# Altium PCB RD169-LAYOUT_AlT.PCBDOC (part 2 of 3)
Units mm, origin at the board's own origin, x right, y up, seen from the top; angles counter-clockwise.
Board outline 192 x 135 mm, 2 copper layers (TOP, BOTTOM), stack 0 mm thick; 266 components, 140 nets, 1304 pads, 0 vias.
Unrouted connection lines stored in the file: 1.
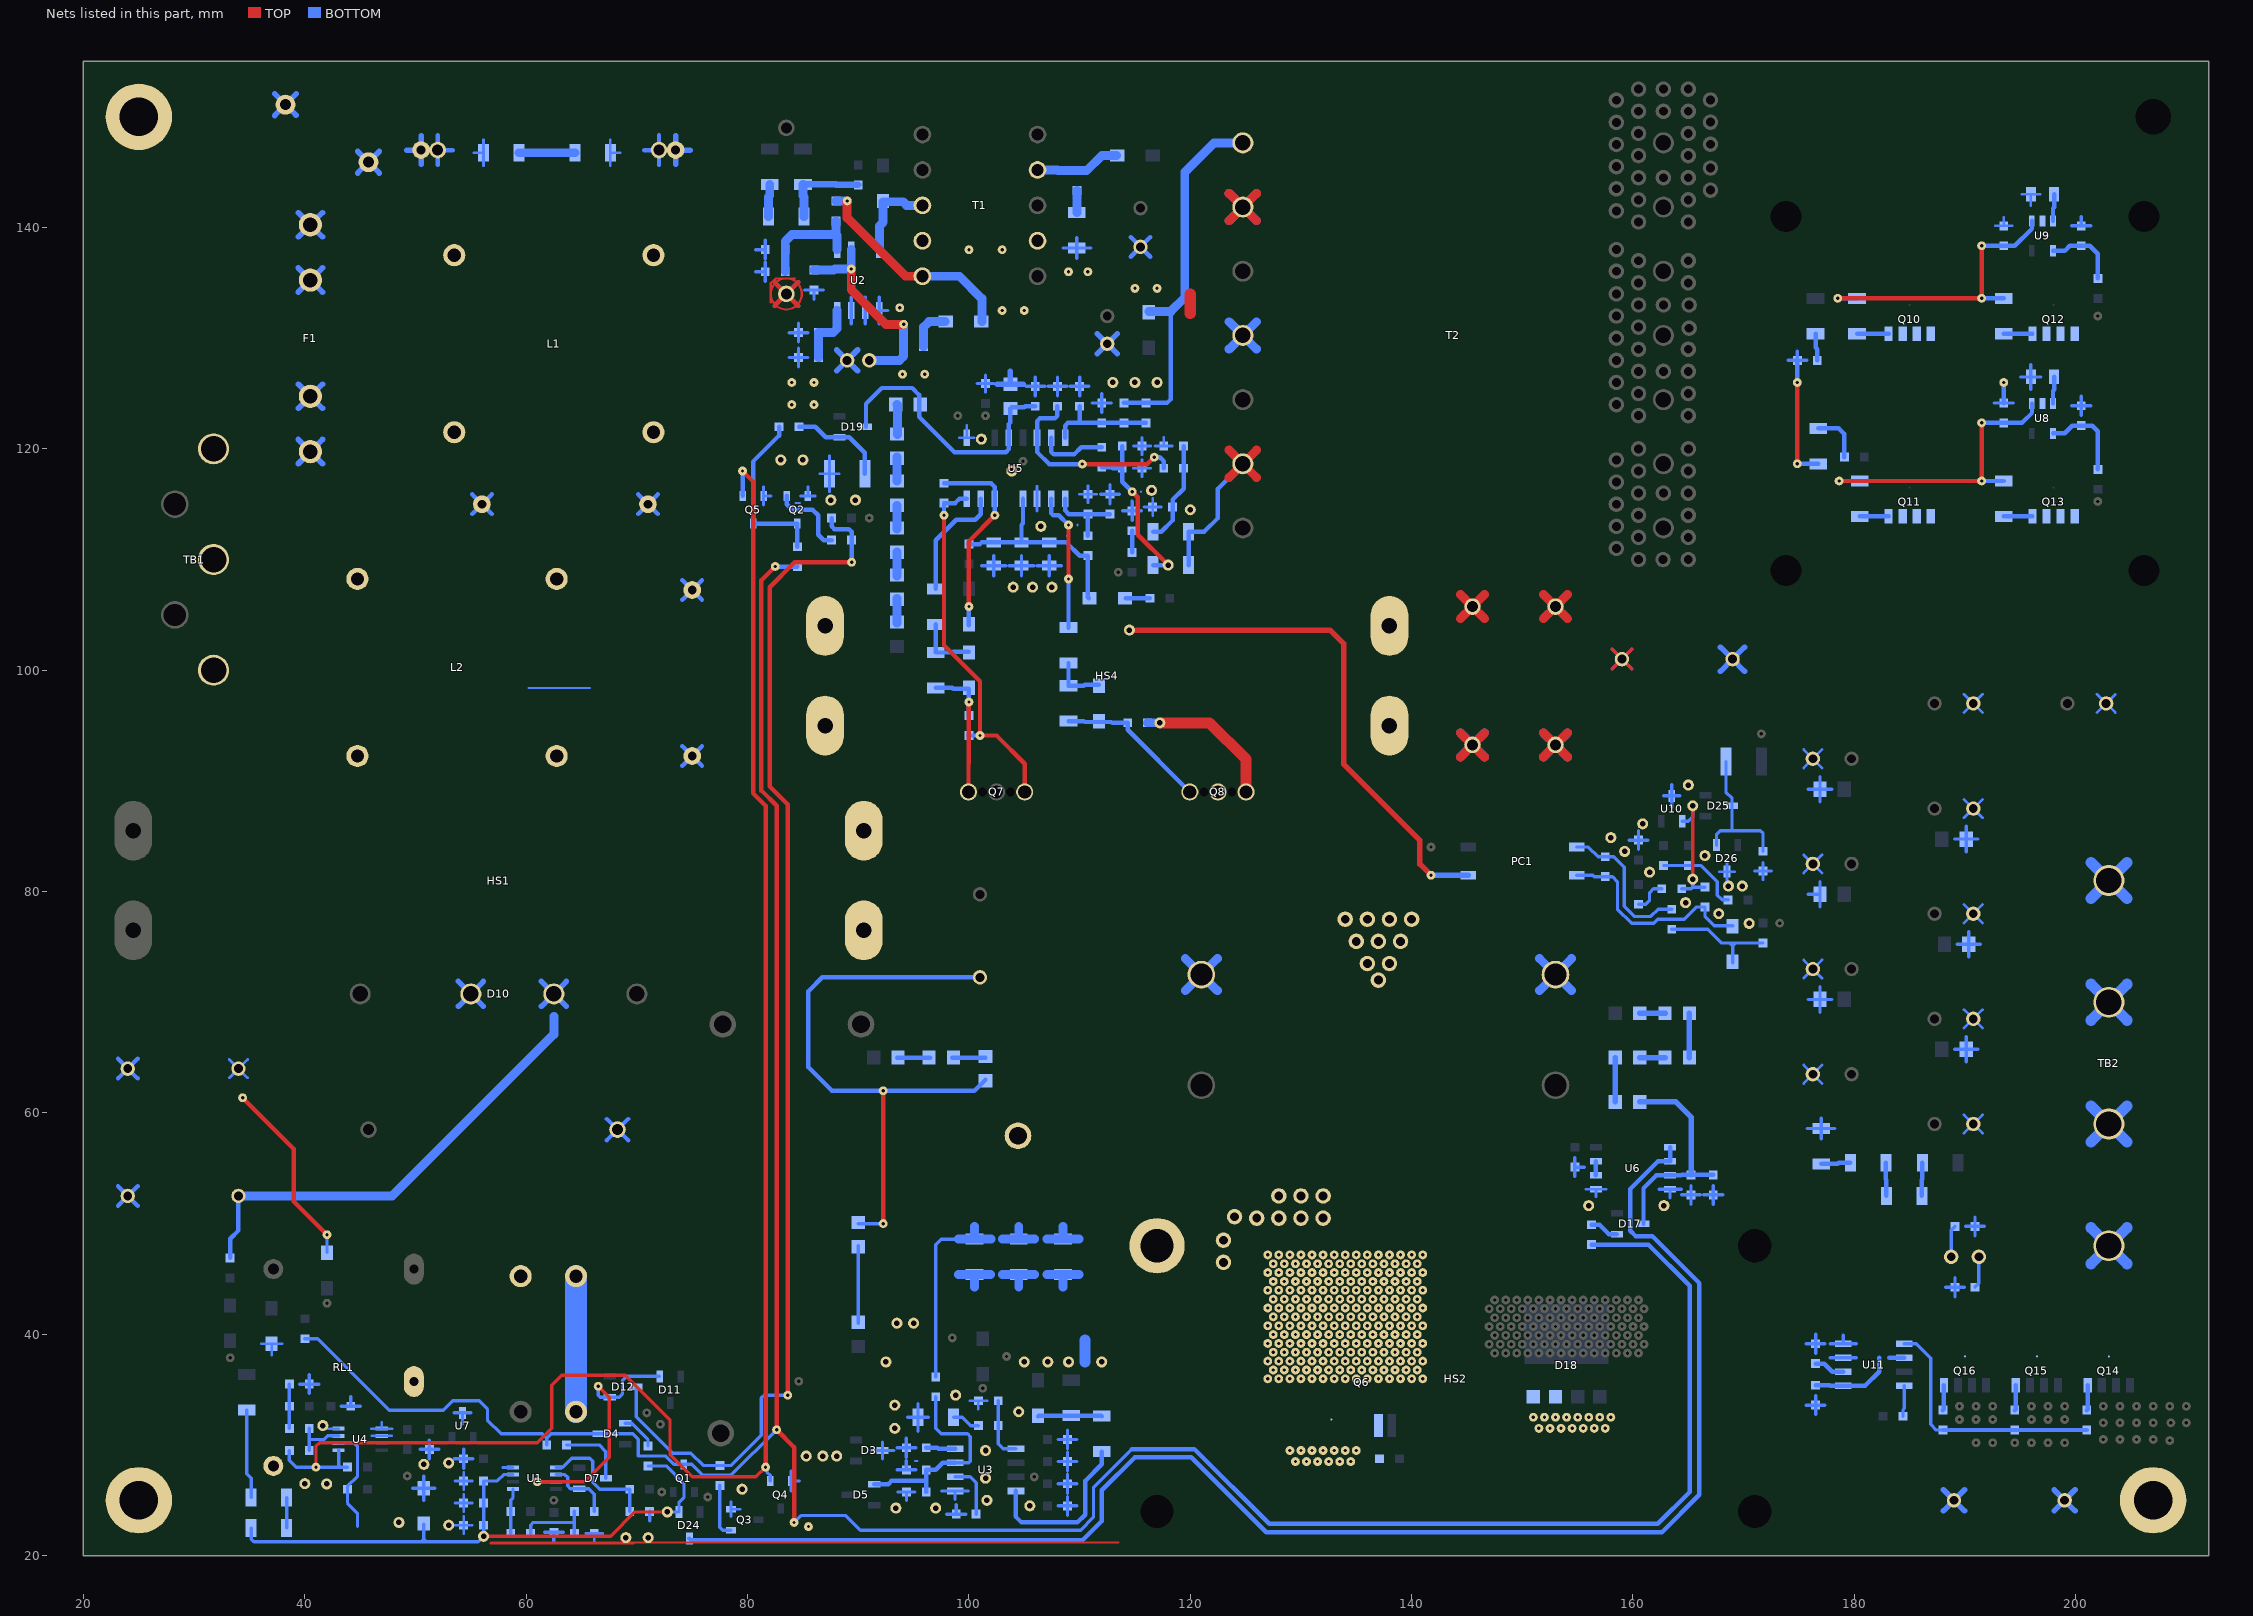
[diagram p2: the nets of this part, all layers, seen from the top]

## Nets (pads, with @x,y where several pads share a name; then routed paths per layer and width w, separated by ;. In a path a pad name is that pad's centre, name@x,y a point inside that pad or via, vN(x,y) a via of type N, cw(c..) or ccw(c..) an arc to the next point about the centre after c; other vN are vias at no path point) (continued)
ACinVDET2: D12.A pad.@83.625,34.5 pad.@89.4,109.75 R28.2 R30.2 R31.2 | length 110.3
  TOP w0.4: pad.@83.625,34.5 83.625,87.875 82,89.5 82,107.5 84.25,109.75 pad.@89.4,109.75
  BOTTOM w0.3: D12.A@69.95,35.25 69.95,32.55 73.25,29.25 74.875,29.25 75.975,28.15 R31.2@77.5,28.15 78.525,28.15 81.25,30.875 81.25,34.25 81.5,34.5 pad.@83.625,34.5
  BOTTOM w0.4: R28.2@87.6,113.75 87.6,113 87.85,112.75 89.15,112.75 89.4,112.5 R30.2@89.4,111.75 pad.@89.4,109.75
BLK: C26.1 D19.A R58.1 R68.2 U5.4 | length 25.3
  BOTTOM w0.4: D19.A@90.7,122 90.7,124.075 92.125,125.5 94.875,125.5 95.5,124.875 95.5,124 95.5,122.9 98.7,119.7 103.325,119.7 103.615,119.99 U5.4@103.615,121 103.615,122.25 103.75,122.385 R58.1@103.75,123.65 103.85,123.75 105,123.75 105.1,123.85 C26.1@106,123.85
BW: D23.A R71.1 R72.1 T2.1 | length 33.8
  BOTTOM w0.4: R72.1@114,124.15 R71.1@116,124.15 117.9,124.15 118.25,124.5 118.25,132.425
  BOTTOM w0.8: D23.A@116.25,132.425 118.25,132.425 119.5,133.675 119.5,145 122.15,147.65 T2.1@124.75,147.65
FG1: C79.1 pad.@207,25 | length 5.4
  BOTTOM w0.5: 198.045,24.045 C79.1@199,25 ; 198.045,25.955 C79.1@199,25 ; 199.955,24.045 C79.1@199,25 ; 199.955,25.955 C79.1@199,25
FG2: pad.@25,150 TB1.3
FG3: C13.2 C15.2 pad.@25,25 | length 10
  BOTTOM w0.4: 23.116,51.616 C15.2@24,52.5 ; 23.116,53.384 C15.2@24,52.5 ; 23.116,63.116 C13.2@24,64 ; 23.116,64.884 C13.2@24,64 ; 24.884,51.616 C15.2@24,52.5 ; 24.884,53.384 C15.2@24,52.5 ; 24.884,63.116 C13.2@24,64 ; 24.884,64.884 C13.2@24,64
GND_PRI_P: C1.2 C10.2 C11.1 C22.1 C25.2 C26.2 C27.2 C28.2 C29.2 C30.2 C31.1 C32.1 C34.2 C36.2 C37.2 C39.2 C41.1 C42.2 C45.2 C47.1 C51.2 C52.2 HS1.1T HS1.2T HS2.1T HS4.1T HS4.2T HS4.3T HS4.4T pad.@83,119 pad.@84,124 pad.@84,126 pad.@85,119 pad.@86,124 pad.@86,126 pad.@87.525,115.375 pad.@89.75,115.375 pad.@93.75,132.75 pad.@94,126.75 pad.@96,126.75 pad.@100,138 pad.@101.125,120.875 pad.@103,132.5 pad.@103,138 pad.@103.875,118.002 pad.@104,107.5 pad.@105,132.5 pad.@105.75,107.5 pad.@106.5,113 pad.@107.5,107.5 pad.@109,136 pad.@110.75,136 pad.@113,126 pad.@114.5,103.625 pad.@115,126 pad.@115,134.5 pad.@116.5,116.25 pad.@117,126 pad.@117,134.5 pad.@117.25,95.25 pad.@120,114.5 pad.@123,46.5 pad.@123,48.5 pad.@124,50.625 pad.@126,50.5 pad.@128,50.5 pad.@128,52.5 pad.@129,29.5 pad.@129.5,28.5 pad.@130,29.5 pad.@130,50.5 pad.@130,52.5 pad.@130.5,28.5 pad.@131,29.5 pad.@131.5,28.5 pad.@132,29.5 pad.@132,50.5 pad.@132,52.5 pad.@132.5,28.5 pad.@133,29.5 pad.@133.5,28.5 pad.@134,29.5 pad.@134,77.5 pad.@134.5,28.5 pad.@135,29.5 pad.@135,75.5 pad.@136,73.5 pad.@136,77.5 pad.@137,72 pad.@137,75.5 pad.@138,73.5 pad.@138,77.5 pad.@139,75.5 pad.@140,77.5 pad.@141.75,81.48 PC1.E Q2.E Q5.E Q6.3 Q8.S R8.2 R13.2 R18.2 R21.2 R33.2 R43.2 R44.2 R45.2 R58.2 R59.2 R80.2 R82.2 R85.2 R86.2 T1.4 T1.7 T2.2 TP1.2 U2.1 U2.2 U2.3 U5.1 U5.11 | length 275.7
  TOP w0.2: 82.1,133.217 82.1,134 ; 84.259,135.4 83.5,135.4 ; 82.1,134 cw(c83.5,134) 82.51,134.99 cw(c83.5,134) 83.5,135.4 ; 82.1,134 ccw(c83.5,134) 82.51,133.01 ccw(c83.5,134) 84.49,133.01 ccw(c83.5,134) 84.9,134 ccw(c83.5,134) 84.49,134.99 ccw(c83.5,134) 83.5,135.4 ; 82.1,134 82.1,134.959 82.541,135.4 83.5,135.4
  TOP w0.3: 158.116,100.116 C47.1@159,101 ; 158.116,101.884 C47.1@159,101 ; 159.884,100.116 C47.1@159,101 ; 159.884,101.884 C47.1@159,101
  TOP w0.4: 82.439,132.939 82.51,133.01 C1.2@83.5,134 ; 82.439,135.061 82.51,134.99 C1.2@83.5,134 ; 84.561,132.939 84.49,133.01 C1.2@83.5,134 ; 84.561,135.061 84.49,134.99 C1.2@83.5,134
  TOP w0.5: pad.@114.5,103.625 132.625,103.625 133.875,102.375 133.875,91.5 140.75,84.625 140.75,82.48 pad.@141.75,81.48
  TOP w0.8: 123.513,140.613 T2.2@124.75,141.85 ; 123.513,143.087 T2.2@124.75,141.85 ; 125.987,140.613 T2.2@124.75,141.85 ; 125.987,143.087 T2.2@124.75,141.85 ; 144.404,92.154 C42.2@145.5,93.25 ; 144.404,94.346 C42.2@145.5,93.25 ; 146.596,92.154 C42.2@145.5,93.25 ; 146.596,94.346 C42.2@145.5,93.25 ; 151.904,92.154 C45.2@153,93.25 ; 151.904,94.346 C45.2@153,93.25 ; 154.096,92.154 C45.2@153,93.25 ; 154.096,94.346 C45.2@153,93.25
  TOP w1: pad.@117.25,95.25 121.75,95.25 125.04,91.96 Q8.S@125.04,89 ; 120,132.25 120,134
  BOTTOM w0.2: 84.338,115.11 84.75,115.11 ; 108.851,112.15 108.877,112.15 ; 108.965,112.325 109.035,112.325 ; 109.8,113.09 109.8,113.16 ; 114.715,115.325 114.785,115.325 ; 115.55,116.09 115.55,116.16
  BOTTOM w0.25: 81.45,114.925 Q5.E@81.45,115.75 ; 81.45,116.575 Q5.E@81.45,115.75 ; 82.125,115.75 Q5.E@81.45,115.75 ; 84.775,115.75 Q2.E@85.45,115.75 ; 85.45,116.575 Q2.E@85.45,115.75 ; 86.125,115.75 Q2.E@85.45,115.75 ; 86.525,117.75 C29.2@87.4,117.75 ; 87.4,116.125 C29.2@87.4,117.75 ; 87.4,119.375 C29.2@87.4,117.75 ; 88.275,117.75 C29.2@87.4,117.75 ; 99.13,121 U5.1@99.805,121 ; 99.805,122.125 U5.1@99.805,121 ; 100.48,121 U5.1@99.805,121 ; 100.725,125.9 C25.2@101.5,125.9 ; 101.5,125.125 C25.2@101.5,125.9 ; 101.5,126.675 C25.2@101.5,125.9 ; 102.275,125.9 C25.2@101.5,125.9 ; 106.155,114.375 U5.11@106.155,115.5 106.155,116.625 ; 109.975,115.9 C34.2@110.75,115.9 ; 110.75,115.125 C34.2@110.75,115.9 ; 110.75,116.675 C34.2@110.75,115.9 ; 111.525,115.9 C34.2@110.75,115.9 ; 114.875,118.25 C51.2@115.65,118.25 ; 114.875,120.25 C52.2@115.65,120.25 ; 115.65,117.475 C51.2@115.65,118.25 ; 115.65,119.025 C51.2@115.65,118.25 ; 115.65,119.475 C52.2@115.65,120.25 ; 115.65,121.025 C52.2@115.65,120.25 ; 115.825,114.75 R86.2@116.6,114.75 ; 116.425,118.25 C51.2@115.65,118.25 ; 116.425,120.25 C52.2@115.65,120.25 ; 116.6,113.975 R86.2@116.6,114.75 ; 116.6,115.525 R86.2@116.6,114.75 ; 116.825,120.25 R85.2@117.6,120.25 ; 117.375,114.75 R86.2@116.6,114.75 ; 117.6,121.025 R85.2@117.6,120.25 ; 118.375,120.25 R85.2@117.6,120.25
  BOTTOM w0.3: 80.75,136 R21.2@81.6,136 ; 80.75,138 R18.2@81.6,138 ; 81.6,135.15 R21.2@81.6,136 ; 81.6,136.85 R21.2@81.6,136 ; 81.6,137.15 R18.2@81.6,138 ; 81.6,138.85 R18.2@81.6,138 ; 83.75,128.25 R13.2@84.6,128.25 ; 83.75,130.5 R8.2@84.6,130.5 ; 84.6,127.4 R13.2@84.6,128.25 ; 84.6,129.1 R13.2@84.6,128.25 ; 84.6,129.65 R8.2@84.6,130.5 ; 84.6,131.35 R8.2@84.6,130.5 ; 85.15,134.35 C10.2@86,134.35 ; 85.45,128.25 R13.2@84.6,128.25 ; 85.45,130.5 R8.2@84.6,130.5 ; 86,133.5 C10.2@86,134.35 ; 86.85,134.35 C10.2@86,134.35 ; 89.365,131.3 U2.3@89.365,132.5 89.365,133.7 ; 90.635,131.3 U2.2@90.635,132.5 90.635,133.7 ; 91.905,131.3 U2.1@91.905,132.5 ; 91.905,133.7 U2.1@91.905,132.5 ; 92.655,132.5 U2.1@91.905,132.5 ; 101.15,109.45 C39.2@102.25,109.45 ; 102.25,108.55 C39.2@102.25,109.45 ; 102.25,110.35 C39.2@102.25,109.45 ; 103.35,109.45 C39.2@102.25,109.45 ; 103.65,109.45 C37.2@104.75,109.45 ; 104.75,108.55 C37.2@104.75,109.45 ; 104.75,110.35 C37.2@104.75,109.45 ; 105.15,125.65 C26.2@106,125.65 ; 105.85,109.45 C37.2@104.75,109.45 ; 106,124.8 C26.2@106,125.65 ; 106,126.5 C26.2@106,125.65 ; 106.15,109.45 C36.2@107.25,109.45 ; 106.85,125.65 C26.2@106,125.65 ; 107.15,125.65 C27.2@108,125.65 ; 107.25,108.55 C36.2@107.25,109.45 ; 107.25,110.35 C36.2@107.25,109.45 ; 108,124.8 C27.2@108,125.65 ; 108,126.5 C27.2@108,125.65 ; 108.35,109.45 C36.2@107.25,109.45 ; 108.5,138.15 R33.2@109.75,138.15 ; 108.85,125.65 C27.2@108,125.65 ; 109.15,125.65 C28.2@110,125.65 ; 109.75,137.2 R33.2@109.75,138.15 ; 109.75,139.1 R33.2@109.75,138.15 ; 110,124.8 C28.2@110,125.65 ; 110,126.5 C28.2@110,125.65 ; 110.85,125.65 C28.2@110,125.65 ; 111,138.15 R33.2@109.75,138.15 ; 111.15,124.15 R59.2@112,124.15 ; 111.9,115.9 R80.2@112.75,115.9 ; 112,123.3 R59.2@112,124.15 ; 112,125 R59.2@112,124.15 ; 112.75,115.05 R80.2@112.75,115.9 ; 112.75,116.75 R80.2@112.75,115.9 ; 112.85,124.15 R59.2@112,124.15 ; 113.6,115.9 R80.2@112.75,115.9 ; 113.9,114.4 C30.2@114.75,114.4 ; 114.75,113.55 C30.2@114.75,114.4 ; 114.75,115.25 C30.2@114.75,114.4 ; 115.6,114.4 C30.2@114.75,114.4 ; 158.116,100.116 C47.1@159,101 ; 158.116,101.884 C47.1@159,101 ; 159.884,100.116 C47.1@159,101 ; 159.884,101.884 C47.1@159,101
  BOTTOM w0.4: 82.439,132.939 C1.2@83.5,134 ; 82.439,135.061 C1.2@83.5,134 ; 84.561,132.939 C1.2@83.5,134 ; 84.561,135.061 C1.2@83.5,134 ; 114.616,137.366 C22.1@115.5,138.25 ; 114.616,139.134 C22.1@115.5,138.25 ; 116.384,137.366 C22.1@115.5,138.25 ; 116.384,139.134 C22.1@115.5,138.25
  BOTTOM w0.5: 88.045,127.045 C11.1@89,128 ; 88.045,128.955 C11.1@89,128 ; 89.955,127.045 C11.1@89,128 ; 89.955,128.955 C11.1@89,128 ; 102.575,125.85 R58.2@103.75,125.85 ; 103.75,127 R58.2@103.75,125.85 ; 104.925,125.85 R58.2@103.75,125.85 ; 111.581,128.581 C41.1@112.5,129.5 ; 111.581,130.419 C41.1@112.5,129.5 ; 113.419,128.581 C41.1@112.5,129.5 ; 113.419,130.419 C41.1@112.5,129.5 ; pad.@141.75,81.48 PC1.E@145.1,81.48
  BOTTOM w0.8: 99.05,45.4 R45.2@100.5,45.4 ; 100.5,44.25 R45.2@100.5,45.4 ; 101.95,45.4 R45.2@100.5,45.4 ; 103.05,45.4 R44.2@104.5,45.4 ; 104.5,44.25 R44.2@104.5,45.4 ; 105.95,45.4 R44.2@104.5,45.4 ; 107.05,45.4 R43.2@108.5,45.4 ; 108.5,44.25 R43.2@108.5,45.4 ; 109.95,45.4 R43.2@108.5,45.4 ; R82.2@116.15,95.25 pad.@117.25,95.25 ; 119.55,71.05 C32.1@121,72.5 ; 119.55,73.95 C32.1@121,72.5 ; 122.45,71.05 C32.1@121,72.5 ; 122.45,73.95 C32.1@121,72.5 ; 123.513,140.613 T2.2@124.75,141.85 ; 123.513,143.087 T2.2@124.75,141.85 ; 125.987,140.613 T2.2@124.75,141.85 ; 125.987,143.087 T2.2@124.75,141.85 ; 144.404,92.154 C42.2@145.5,93.25 ; 144.404,94.346 C42.2@145.5,93.25 ; 146.596,92.154 C42.2@145.5,93.25 ; 146.596,94.346 C42.2@145.5,93.25 ; 151.55,71.05 C31.1@153,72.5 ; 151.55,73.95 C31.1@153,72.5 ; 151.904,92.154 C45.2@153,93.25 ; 151.904,94.346 C45.2@153,93.25 ; 154.096,92.154 C45.2@153,93.25 ; 154.096,94.346 C45.2@153,93.25 ; 154.45,71.05 C31.1@153,72.5 ; 154.45,73.95 C31.1@153,72.5
GND_PRI_S: C2.2 C3.2 C6.2 C7.2 C8.2 C14.2 C16.2 C17.2 C19.2 C20.2 C21.2 C33.2 C35.2 C40.2 C43.2 D3.A D13.A pad.@40,26.5 pad.@41.625,31.75 pad.@41.975,26.475 pad.@48.5,23 pad.@50.75,28.25 pad.@53,22.75 pad.@53,28.375 pad.@69,21.625 pad.@71.025,21.625 pad.@79.5,26 pad.@85.3,29 pad.@85.5,22.625 pad.@86.8,29 pad.@88.05,29 pad.@92.5,37.5 pad.@93.3,31.5 pad.@93.3,33.6 pad.@93.4,24.3 pad.@93.5,41 pad.@95,41 pad.@97,24.3 pad.@98.8,34.5 pad.@101.5,27 pad.@101.5,29.5 pad.@101.625,25 pad.@104.5,33 pad.@105,37.5 pad.@105.5,24.5 pad.@107.125,37.5 pad.@109,37.5 pad.@112,37.5 pad.@156,51.625 pad.@162.8,51.625 Q3.E Q4.E Q6.2 R1.2 R5.2 R15.2 R20.2 R25.2 R41.2 R49.1 R57.2 R61.2 RL1.2 TP1.1 U1.4 U3.1 U4.4 U4.5 U4.6 U6.4 U6.5 U7.3 ZD1.A | length 183.1
  TOP w0.2: 56.905,21.19 113.499,21.19 ; 67.601,21.2 56.863,21.2 56.814,21.141 56.773,21.1 69.675,21.1
  BOTTOM w0.2: 95.15,28.55 95.35,28.55
  BOTTOM w0.25: 36.075,39.15 D13.A@37,39.15 ; 37,38.125 D13.A@37,39.15 ; 37.925,39.15 D13.A@37,39.15 ; 42.125,31.475 U4.4@43.05,31.475 ; 46.025,31.475 U4.5@46.95,31.475 ; 46.05,30.825 U4.6@46.95,30.825 47.85,30.825 ; 46.95,32.025 U4.5@46.95,31.475 ; 47.875,31.475 U4.5@46.95,31.475 ; 53.575,22.75 R5.2@54.35,22.75 ; 53.575,24.75 C2.2@54.35,24.75 ; 53.575,26.75 R1.2@54.35,26.75 ; 54.35,21.975 R5.2@54.35,22.75 ; 54.35,23.525 R5.2@54.35,22.75 ; 54.35,23.975 C2.2@54.35,24.75 ; 54.35,25.525 C2.2@54.35,24.75 ; 54.35,25.975 R1.2@54.35,26.75 ; 54.35,27.525 R1.2@54.35,26.75 ; 55.125,22.75 R5.2@54.35,22.75 ; 55.125,24.75 C2.2@54.35,24.75 ; 55.125,26.75 R1.2@54.35,26.75 ; 57.875,27.975 U1.4@58.8,27.975 ; 65.375,22 C8.2@66.15,22 ; 66.15,21.225 C8.2@66.15,22 ; 66.925,22 C8.2@66.15,22 ; 78.5,23.525 Q3.E@78.5,24.2 ; 78.5,24.875 Q3.E@78.5,24.2 ; 79.325,24.2 Q3.E@78.5,24.2 ; 93.575,25.75 R15.2@94.35,25.75 ; 94.35,24.975 R15.2@94.35,25.75 ; 95.125,25.75 R15.2@94.35,25.75 ; 100.075,34 C16.2@100.85,34 ; 100.85,33.225 C16.2@100.85,34 ; 101.625,34 C16.2@100.85,34 ; 155.725,53.095 U6.5@156.65,53.095 ; 156.65,52.42 U6.5@156.65,53.095 ; 157.575,53.095 U6.5@156.65,53.095
  BOTTOM w0.3: 39.55,35.5 R61.2@40.4,35.5 ; 40.4,34.65 R61.2@40.4,35.5 ; 40.4,36.35 R61.2@40.4,35.5 ; 41.25,35.5 R61.2@40.4,35.5 ; 43.3,33.5 C33.2@44.15,33.5 ; 44.15,34.35 C33.2@44.15,33.5 ; 45,33.5 C33.2@44.15,33.5 ; 49.75,26.1 ZD1.A@50.75,26.1 ; 50.4,29.6 C43.2@51.25,29.6 ; 50.75,25 ZD1.A@50.75,26.1 ; 50.75,27.2 ZD1.A@50.75,26.1 ; 51.25,28.75 C43.2@51.25,29.6 ; 51.25,30.45 C43.2@51.25,29.6 ; 51.75,26.1 ZD1.A@50.75,26.1 ; 52.1,29.6 C43.2@51.25,29.6 ; 53.5,28.75 C3.2@54.35,28.75 ; 53.5,32.9 U7.3@54.25,32.9 ; 54.25,31.9 U7.3@54.25,32.9 ; 54.35,27.9 C3.2@54.35,28.75 ; 54.35,29.6 C3.2@54.35,28.75 ; 55,32.9 U7.3@54.25,32.9 ; 55.2,28.75 C3.2@54.35,28.75 ; 61.65,22.1 C17.2@62.5,22.1 ; 62.5,21.25 C17.2@62.5,22.1 ; 63.35,22.1 C17.2@62.5,22.1 ; 71.15,23.15 R25.2@71.15,24 ; 83.95,25.85 Q4.E@83.95,26.75 ; 83.95,27.65 Q4.E@83.95,26.75 ; 84.7,26.75 Q4.E@83.95,26.75 ; 91.2,29.5 D3.A@92.2,29.5 ; 92.2,28.75 D3.A@92.2,29.5 ; 92.2,30.25 D3.A@92.2,29.5 ; 93.2,29.5 D3.A@92.2,29.5 ; 93.5,27.75 C6.2@94.35,27.75 ; 93.5,29.75 R20.2@94.35,29.75 ; 94.35,28.6 C6.2@94.35,27.75 ; 94.35,28.9 R20.2@94.35,29.75 ; 94.35,30.6 R20.2@94.35,29.75 ; 94.45,32.5 C14.2@95.4,32.5 ; 95.2,27.75 C6.2@94.35,27.75 ; 95.2,29.75 R20.2@94.35,29.75 ; 95.4,31.25 C14.2@95.4,32.5 ; 95.4,33.75 C14.2@95.4,32.5 ; 96.35,32.5 C14.2@95.4,32.5 ; 97.55,25.845 U3.1@98.75,25.845 ; 98,23.75 C7.2@98.85,23.75 ; 98.75,25.095 U3.1@98.75,25.845 ; 98.85,24.6 C7.2@98.85,23.75 ; 99.7,23.75 C7.2@98.85,23.75 ; 99.95,25.845 U3.1@98.75,25.845 ; 108.05,24.5 C19.2@108.9,24.5 ; 108.05,26.5 C20.2@108.9,26.5 ; 108.05,28.5 R41.2@108.9,28.5 ; 108.05,30.5 C21.2@108.9,30.5 ; 108.9,23.65 C19.2@108.9,24.5 ; 108.9,25.35 C19.2@108.9,24.5 ; 108.9,25.65 C20.2@108.9,26.5 ; 108.9,27.35 C20.2@108.9,26.5 ; 108.9,27.65 R41.2@108.9,28.5 ; 108.9,29.35 R41.2@108.9,28.5 ; 108.9,29.65 C21.2@108.9,30.5 ; 108.9,31.35 C21.2@108.9,30.5 ; 109.75,24.5 C19.2@108.9,24.5 ; 109.75,26.5 C20.2@108.9,26.5 ; 109.75,28.5 R41.2@108.9,28.5 ; 109.75,30.5 C21.2@108.9,30.5 ; 154.75,54.25 C40.2@154.75,55.1 ; 154.75,55.95 C40.2@154.75,55.1 ; 155.6,55.1 C40.2@154.75,55.1 ; 162.35,53.095 U6.4@163.35,53.095 ; 163.35,52.345 U6.4@163.35,53.095 ; 164.35,53.095 U6.4@163.35,53.095 ; 164.4,52.6 R57.2@165.25,52.6 ; 165.25,51.75 R57.2@165.25,52.6 ; 165.25,53.45 R57.2@165.25,52.6 ; 166.1,52.6 R57.2@165.25,52.6 ; 166.4,52.6 C35.2@167.25,52.6 ; 167.25,51.75 C35.2@167.25,52.6 ; 167.25,53.45 C35.2@167.25,52.6 ; 168.1,52.6 C35.2@167.25,52.6
  BOTTOM w1: 110.5,37.5 TP1.1@110.5,39.5
GND_SEC: C47.2 C50.1 C53.2 C54.2 C55.2 C56.1 C57.1 C58.2 C59.1 C60.1 C61.1 C62.1 C63.1 C65.2 C66.1 C67.1 C69.1 C71.2 C72.2 C74.2 C75.2 C76.2 C77.2 C78.1 C79.2 C80.2 C81.2 D26.A pad.@158,84.875 pad.@159.25,83.625 pad.@160.875,86.125 pad.@161.5,81.75 pad.@164.75,79 pad.@165,89.625 pad.@166.5,83.25 pad.@167.75,78 pad.@168.625,80.5 pad.@169.875,80.5 pad.@170.5,77.125 pad.@174.85,118.65 pad.@174.85,126 pad.@193.5,126 Q10.1 Q10.2 Q10.3 Q11.1 Q11.2 Q11.3 Q12.1 Q12.2 Q12.3 Q13.1 Q13.2 Q13.3 R89.2 R91.1 R96.1 R104.2 R108.2 R109.1 R114.2 TB2.1 TB2.2 U8.2 U9.2 U10.3 U11.3 U11.4 | length 171.1
  TOP w0.4: pad.@174.85,118.65 pad.@174.85,126
  BOTTOM w0.25: 167.825,81.8 D26.A@168.5,81.8 ; pad.@168.5,80.875 D26.A@168.5,81.8 ; 168.5,82.725 D26.A@168.5,81.8 ; 169.175,81.8 D26.A@168.5,81.8 ; 170.975,81.85 R114.2@171.75,81.85 ; 171.75,81.075 R114.2@171.75,81.85 ; 171.75,82.625 R114.2@171.75,81.85 ; 172.525,81.85 R114.2@171.75,81.85 ; 175.419,62.669 C69.1@176.25,63.5 ; 175.419,64.331 C69.1@176.25,63.5 ; 175.419,72.169 C67.1@176.25,73 ; 175.419,73.831 C67.1@176.25,73 ; 175.419,81.669 C66.1@176.25,82.5 ; 175.419,83.331 C66.1@176.25,82.5 ; 175.419,91.169 C63.1@176.25,92 ; 175.419,92.831 C63.1@176.25,92 ; 177.081,62.669 C69.1@176.25,63.5 ; 177.081,64.331 C69.1@176.25,63.5 ; 177.081,72.169 C67.1@176.25,73 ; 177.081,73.831 C67.1@176.25,73 ; 177.081,81.669 C66.1@176.25,82.5 ; 177.081,83.331 C66.1@176.25,82.5 ; 177.081,91.169 C63.1@176.25,92 ; 177.081,92.831 C63.1@176.25,92 ; 189.919,58.169 C62.1@190.75,59 ; 189.919,59.831 C62.1@190.75,59 ; 189.919,67.669 C61.1@190.75,68.5 ; 189.919,69.331 C61.1@190.75,68.5 ; 189.919,77.169 C60.1@190.75,78 ; 189.919,78.831 C60.1@190.75,78 ; 189.919,86.669 C59.1@190.75,87.5 ; 189.919,88.331 C59.1@190.75,87.5 ; 189.919,96.169 C57.1@190.75,97 ; 189.919,97.831 C57.1@190.75,97 ; 191.581,58.169 C62.1@190.75,59 ; 191.581,59.831 C62.1@190.75,59 ; 191.581,67.669 C61.1@190.75,68.5 ; 191.581,69.331 C61.1@190.75,68.5 ; 191.581,77.169 C60.1@190.75,78 ; 191.581,78.831 C60.1@190.75,78 ; 191.581,86.669 C59.1@190.75,87.5 ; 191.581,88.331 C59.1@190.75,87.5 ; 191.581,96.169 C57.1@190.75,97 ; 191.581,97.831 C57.1@190.75,97 ; 192.725,140.15 R96.1@193.5,140.15 ; 193.5,140.925 R96.1@193.5,140.15 ; 194.275,140.15 R96.1@193.5,140.15 ; 195.125,143 C55.2@195.95,143 ; 195.95,141.975 C55.2@195.95,143 ; 196.775,143 C55.2@195.95,143 ; 201.919,96.169 C56.1@202.75,97 ; 201.919,97.831 C56.1@202.75,97 ; 203.581,96.169 C56.1@202.75,97 ; 203.581,97.831 C56.1@202.75,97
  BOTTOM w0.3: 159.65,84.65 R108.2@160.5,84.65 ; 160.5,83.8 R108.2@160.5,84.65 ; 160.5,85.5 R108.2@160.5,84.65 ; 161.35,84.65 R108.2@160.5,84.65 ; 162.75,88.65 U10.3@163.5,88.65 ; 163.5,87.65 U10.3@163.5,88.65 ; 163.5,89.65 U10.3@163.5,88.65 ; 164.25,88.65 U10.3@163.5,88.65 ; 174,128 C50.1@174.85,128 ; 174.85,128.85 C50.1@174.85,128 ; 175.65,33.6 C65.2@176.5,33.6 ; 175.65,39.15 R104.2@176.5,39.15 ; 175.7,128 C50.1@174.85,128 ; 175.75,58.6 R109.1@177,58.6 ; 175.85,70.25 C77.2@176.9,70.25 ; 175.85,79.75 C76.2@176.9,79.75 ; 175.85,89.25 C75.2@176.9,89.25 ; 176.5,32.75 C65.2@176.5,33.6 ; 176.5,34.45 C65.2@176.5,33.6 ; 176.5,38.3 R104.2@176.5,39.15 ; 176.5,40 R104.2@176.5,39.15 ; 176.9,69.1 C77.2@176.9,70.25 ; 176.9,71.4 C77.2@176.9,70.25 ; 176.9,78.6 C76.2@176.9,79.75 ; 176.9,80.9 C76.2@176.9,79.75 ; 176.9,88.1 C75.2@176.9,89.25 ; 176.9,90.4 C75.2@176.9,89.25 ; 177,57.65 R109.1@177,58.6 ; 177,59.55 R109.1@177,58.6 ; 177.35,33.6 C65.2@176.5,33.6 ; 177.35,39.15 R104.2@176.5,39.15 ; 177.8,37.885 U11.3@179,37.885 180.2,37.885 ; 177.8,39.155 U11.4@179,39.155 ; 177.95,70.25 C77.2@176.9,70.25 ; 177.95,89.25 C75.2@176.9,89.25 ; 178.25,58.6 R109.1@177,58.6 ; 179,39.9 U11.4@179,39.155 ; 180.2,39.155 U11.4@179,39.155 ; 189.05,65.75 C74.2@190.1,65.75 ; 189.05,84.75 C71.2@190.1,84.75 ; 189.3,75.25 C72.2@190.35,75.25 ; 190.05,49.75 C81.2@190.9,49.75 ; 190.1,64.6 C74.2@190.1,65.75 ; 190.1,66.9 C74.2@190.1,65.75 ; 190.1,83.6 C71.2@190.1,84.75 ; 190.1,85.9 C71.2@190.1,84.75 ; 190.35,74.1 C72.2@190.35,75.25 ; 190.35,76.4 C72.2@190.35,75.25 ; C80.2@190.9,44.25 191.25,44.6 C78.1@191.25,47 C78.1@191.25,47.125 ; 190.9,48.9 C81.2@190.9,49.75 ; 190.9,50.6 C81.2@190.9,49.75 ; 191.15,65.75 C74.2@190.1,65.75 ; 191.15,84.75 C71.2@190.1,84.75 ; 191.4,75.25 C72.2@190.35,75.25 ; 191.75,49.75 C81.2@190.9,49.75 ; 192.65,124.15 R91.1@193.5,124.15 194.35,124.15 ; 195.05,126.5 C53.2@195.95,126.5 ; 195.95,125.4 C53.2@195.95,126.5 ; 195.95,127.6 C53.2@195.95,126.5 ; 196.85,126.5 C53.2@195.95,126.5 ; 199.65,123.9 C54.2@200.5,123.9 ; 199.65,140.15 C58.2@200.5,140.15 ; 200.5,123.05 C54.2@200.5,123.9 ; 200.5,124.75 C54.2@200.5,123.9 ; 200.5,141 C58.2@200.5,140.15 ; 201.35,123.9 C54.2@200.5,123.9 ; 201.35,140.15 C58.2@200.5,140.15
  BOTTOM w0.4: pad.@174.85,118.65 R89.2@176.75,118.65 ; pad.@174.85,126 C50.1@174.85,128 ; R91.1@193.5,124.1 R91.1@193.5,124.15 pad.@193.5,126
  BOTTOM w0.5: 167.904,99.904 C47.2@169,101 ; 167.904,102.096 C47.2@169,101 ; 170.096,99.904 C47.2@169,101 ; 170.096,102.096 C47.2@169,101 ; 188.045,24.045 C79.2@189,25 ; 188.045,25.955 C79.2@189,25 ; 189.955,24.045 C79.2@189,25 ; 189.955,25.955 C79.2@189,25
  BOTTOM w1: 201.374,68.374 TB2.2@203,70 ; 201.374,71.626 TB2.2@203,70 ; 201.374,79.374 TB2.1@203,81 ; 201.374,82.626 TB2.1@203,81 ; 204.626,68.374 TB2.2@203,70 ; 204.626,71.626 TB2.2@203,70 ; 204.626,79.374 TB2.1@203,81 ; 204.626,82.626 TB2.1@203,81
Hi_Gate: R74.2 U5.15 | length 10.8
  BOTTOM w0.4: R74.2@97,107.35 97,111.75 98.85,113.6 100.575,113.6 101.075,114.1 U5.15@101.075,115.5
HS: C38.1 pad.@97.75,114 pad.@101,94.1 Q7.S Q8.D R81.2 T2.4 U5.16 | length 40.2
  TOP w0.4: pad.@97.75,114 97.75,102.25 101,99 pad.@101,94.1 102.5,94.1 105.04,91.56 Q7.S@105.04,89
  BOTTOM w0.4: pad.@97.75,114 C38.1@97.75,115.1 98.75,115.1 99.15,115.5 U5.16@99.805,115.5 ; R81.2@100,94.1 pad.@101,94.1
  BOTTOM w0.8: 123.513,129.013 T2.4@124.75,130.25 ; 123.513,131.487 T2.4@124.75,130.25 ; 125.987,129.013 T2.4@124.75,130.25 ; 125.987,131.487 T2.4@124.75,130.25
HV+SENS: C35.1 D17.A R56.2 R57.1 U6.3 | length 20.4
  BOTTOM w0.4: D17.A@160.95,50 160.95,53.2 162.115,54.365 U6.3@163.35,54.365 164.375,54.365 164.41,54.4 R57.1@165.25,54.4 C35.1@167.25,54.4
  BOTTOM w0.5: R56.2@160.6,61 163.875,61 165.25,59.625 R57.1@165.25,54.4
HVdet: C2.1 D24.C pad.@56.15,21.75 pad.@72.75,23.95 R1.1 R4.2 R5.1 R9.1 U1.3 ZD1.C | length 57.4
  TOP w0.3: pad.@56.15,21.75 67.625,21.75 69.825,23.95 pad.@72.75,23.95
  BOTTOM w0.3: R4.2@35.15,22.5 35.15,21.5 35.4,21.25 50.5,21.25 ; ZD1.C@50.75,22.825 50.75,21.5 ; U1.3@58.8,27.325 57.95,27.325 57.375,26.75 R1.1@56.15,26.75 C2.1@56.15,24.75 R5.1@56.15,22.75 pad.@56.15,21.75 55.65,21.25 51,21.25 ; R9.1@71,28.1 72.65,28.1 74.25,26.5 74.25,25.25 73.8,24.8 D24.C@73.8,23.95 pad.@72.75,23.95 ; 50.5,21.25 50.75,21.5 ; 50.5,21.25 51,21.25 ; 50.75,21.5 51,21.25
ISENSE: C23.2 R19.1 R35.1 R43.1 R44.1 R45.1 RL1.3 | length 31.8
  BOTTOM w0.3: R19.1@97,36.15 97,48.1 97.5,48.6 99.05,48.6
  BOTTOM w0.4: 67.295,57.545 C23.2@68.25,58.5 ; 67.295,59.455 C23.2@68.25,58.5 ; 69.205,57.545 C23.2@68.25,58.5 ; 69.205,59.455 C23.2@68.25,58.5
  BOTTOM w0.8: 99.05,48.6 R45.1@100.5,48.6 ; 100.5,49.75 R45.1@100.5,48.6 ; 102,48.6 R45.1@100.5,48.6 ; 103.05,48.6 R44.1@104.5,48.6 ; 104.5,49.75 R44.1@104.5,48.6 ; 105.95,48.6 R44.1@104.5,48.6 ; 107.05,48.6 R43.1@108.5,48.6 ; 108.5,49.75 R43.1@108.5,48.6 ; 109.95,48.6 R43.1@108.5,48.6
ISNS_VCR: C42.1 C44.1 C45.1 C46.1 T2.6 | length 31.4
  TOP w0.8: 123.513,117.413 T2.6@124.75,118.65 ; 123.513,119.887 T2.6@124.75,118.65 ; 125.987,117.413 T2.6@124.75,118.65 ; 125.987,119.887 T2.6@124.75,118.65 ; 144.404,104.654 C42.1@145.5,105.75 ; 144.404,106.846 C42.1@145.5,105.75 ; 146.596,104.654 C42.1@145.5,105.75 ; 146.596,106.846 C42.1@145.5,105.75 ; 151.904,104.654 C45.1@153,105.75 ; 151.904,106.846 C45.1@153,105.75 ; 154.096,104.654 C45.1@153,105.75 ; 154.096,106.846 C45.1@153,105.75
  BOTTOM w0.4: C44.1@119.85,109.5 C46.1@119.85,112.5 121.25,112.5 122.5,113.75 122.5,116.4 T2.6@124.75,118.65
Lo_Gate: pad.@109,108.25 pad.@109,113.125 R76.2 U5.10 | length 12.6
  TOP w0.4: pad.@109,108.25 pad.@109,113.125
  BOTTOM w0.4: U5.10@107.425,115.5 107.425,114.2 107.625,114 108.125,114 pad.@109,113.125 ; R76.2@109,103.85 pad.@109,108.25
OR_Gate: R113.2 R115.2 R116.2 U11.5 | length 23.2
  BOTTOM w0.3: U11.5@184.5,39.155 185.595,39.155 186.9,37.85 186.9,31.85 187.4,31.35 R116.2@188,31.35
  BOTTOM w0.4: R116.2@188,31.35 R115.2@194.5,31.35 R113.2@201,31.35
OTP: pad.@41,28 pad.@79.55,118 pad.@81.625,28 Q4.B Q5.B R69.2 R75.2 U4.1 | length 155.9
  TOP w0.3: pad.@41,28 41,29.875 41.325,30.2 61,30.2 62.3,31.5 62.3,35.4 63.2,36.3 68.95,36.3 73,32.25 73,29.125 75,27.125 80.75,27.125 pad.@81.625,28
  TOP w0.4: pad.@79.55,118 80.5,117.05 80.5,88.875 81.625,87.75 pad.@81.625,28
  BOTTOM w0.3: R69.2@38.6,29.5 38.6,28.625 39.225,28 pad.@41,28 43.05,28 ; U4.1@43.05,29.525 43.05,28 ; R75.2@43.85,28 43.05,28 ; pad.@81.625,28 81.75,27.875 81.75,27.55 82.05,27.25 Q4.B@82.05,26.75
  BOTTOM w0.4: Q5.B@79.55,115.75 pad.@79.55,118
PC1_A: PC1.A R101.2 R102.1 | length 13.5
  BOTTOM w0.3: PC1.A@154.9,84.02 155.98,84.02 156.85,83.15 R102.1@157.5,83.15 158.25,83.15 159.2,82.2 159.2,78.675 160.125,77.75 161.625,77.75 162.275,78.4 R101.2@163.5,78.4
PC1_CA: PC1.CA R102.2 R103.1 ZD3.A | length 19.2
  BOTTOM w0.3: PC1.CA@154.9,81.48 156.375,81.48 156.505,81.35 R102.2@157.5,81.35 158.15,81.35 158.6,80.9 158.6,78.4 159.875,77.125 161.875,77.125 162.25,77.5 164.625,77.5 165.725,78.6 R103.1@166.5,78.6 166.5,77.75 167.325,76.925 ZD3.A@169,76.925
PFC_Gate: D16.C R42.1 R46.1 | length 5.8
  BOTTOM w0.4: D16.C@106.25,32.575 106.325,32.65 R46.1@109.25,32.65 111.95,32.65 R42.1@112,32.6
Relay_12V_ON_OFF: D4.A pad.@82.5,109.375 pad.@82.625,31.375 pad.@84.2,23 Q1.C R27.2 R32.2 R47.1 R50.1 | length 262.1
  TOP w0.4: pad.@82.5,109.375 81.25,108.125 81.25,89.125 82.625,87.75 pad.@82.625,31.375 84.2,29.8 pad.@84.2,23
  BOTTOM w0.3: R32.2@40,39.6 41.15,39.6 47.625,33.125 52.5,33.125 53.375,34 55.75,34 56.5,33.25 56.5,32.25 57.75,31 61.45,31 61.85,30.6 ; R27.2@61.85,30 61.85,30.6 ; pad.@82.625,31.375 78.5,27.25 75.95,27.25 74.95,28.25 Q1.C@74.25,28.25 73.35,28.25 72.6,29 70.125,29 70.125,30.5 69.625,31 D4.A@66.55,31 62.25,31 61.85,30.6 ; pad.@84.2,23 84.825,23.625 88.875,23.625 90.2,22.3 110.1,22.3 111.25,23.45 111.25,26.15 114.725,29.625
  BOTTOM w0.4: pad.@82.5,109.375 82.525,109.35 R50.1@84.5,109.35 ; 114.725,29.625 120.375,29.625 127.125,22.875 162.25,22.875 165.125,25.75 165.125,44.375 161.4,48.1 R47.1@156.25,48.1
RVCC: C36.1 C37.1 C39.1 R79.1 R83.2 U5.12 ZD2.C | length 19.2
  BOTTOM w0.4: R83.2@100,111.4 101,111.4 101.15,111.55 C39.1@102.25,111.55 C37.1@104.75,111.55 ; U5.12@104.885,115.5 104.885,113.26 104.75,113.125 C37.1@104.75,111.55 ; ZD2.C@110.825,106.5 110.75,106.575 R79.1@110.75,110.35 110.025,110.35 108.825,111.55 C36.1@107.25,111.55 C37.1@104.75,111.55
SIG219: C9.1 L1.3 L2.4 | length 5
  BOTTOM w0.4: 70.116,114.116 C9.1@71,115 ; 70.116,115.884 C9.1@71,115 ; 71.884,114.116 C9.1@71,115 ; 71.884,115.884 C9.1@71,115
SIG222: C12.1 C15.1 D10.3 L2.3 R12.1 | length 53.5
  BOTTOM w0.4: R12.1@33.25,46.9 33.25,48.625 34,49.375 C15.1@34,52.5 ; 74.116,91.366 C12.1@75,92.25 ; 74.116,93.134 C12.1@75,92.25 ; 75.884,91.366 C12.1@75,92.25 ; 75.884,93.134 C12.1@75,92.25
  BOTTOM w0.5: 61.369,69.619 D10.3@62.5,70.75 ; 61.369,71.881 D10.3@62.5,70.75 ; 63.631,69.619 D10.3@62.5,70.75 ; 63.631,71.881 D10.3@62.5,70.75
  BOTTOM w0.8: C15.1@34,52.5 47.9,52.5 62.5,67.1 62.5,68.7
SIG226: C12.2 C13.1 D2.A D10.2 L2.2 pad.@34.375,61.375 pad.@42,49 | length 38.7
  TOP w0.4: pad.@34.375,61.375 39,56.75 39,52 pad.@42,49
  BOTTOM w0.2: 60.225,98.4 65.75,98.4
  BOTTOM w0.25: 33.169,63.169 C13.1@34,64 ; 33.169,64.831 C13.1@34,64 ; 34.831,63.169 C13.1@34,64 ; 34.831,64.831 C13.1@34,64
  BOTTOM w0.3: D2.A@42,47.425 pad.@42,49
  BOTTOM w0.4: 74.116,106.366 C12.2@75,107.25 ; 74.116,108.134 C12.2@75,107.25 ; 75.884,106.366 C12.2@75,107.25 ; 75.884,108.134 C12.2@75,107.25
  BOTTOM w0.5: 53.869,69.619 D10.2@55,70.75 ; 53.869,71.881 D10.2@55,70.75 ; 56.131,69.619 D10.2@55,70.75 ; 56.131,71.881 D10.2@55,70.75
SIG231: D18.3 D18.4 L3.2 pad.@127,35.975 pad.@127,37.575 pad.@127,39.175 pad.@127,40.775 pad.@127,42.375 pad.@127,43.975 pad.@127,45.575 pad.@127,47.175 pad.@127.5,36.775 pad.@127.5,38.375 pad.@127.5,39.975 pad.@127.5,41.575 pad.@127.5,43.175 pad.@127.5,44.775 pad.@127.5,46.375 pad.@128,35.975 pad.@128,37.575 pad.@128,39.175 pad.@128,40.775 pad.@128,42.375 pad.@128,43.975 pad.@128,45.575 pad.@128,47.175 pad.@128.5,36.775 pad.@128.5,38.375 pad.@128.5,39.975 pad.@128.5,41.575 pad.@128.5,43.175 pad.@128.5,44.775 pad.@128.5,46.375 pad.@129,35.975 pad.@129,37.575 pad.@129,39.175 pad.@129,40.775 pad.@129,42.375 pad.@129,43.975 pad.@129,45.575 pad.@129,47.175 pad.@129.5,36.775 pad.@129.5,38.375 pad.@129.5,39.975 pad.@129.5,41.575 pad.@129.5,43.175 pad.@129.5,44.775 pad.@129.5,46.375 pad.@130,35.975 pad.@130,37.575 pad.@130,39.175 pad.@130,40.775 pad.@130,42.375 pad.@130,43.975 pad.@130,45.575 pad.@130,47.175 pad.@130.5,36.775 pad.@130.5,38.375 pad.@130.5,39.975 pad.@130.5,41.575 pad.@130.5,43.175 pad.@130.5,44.775 pad.@130.5,46.375 pad.@131,35.975 pad.@131,37.575 pad.@131,39.175 pad.@131,40.775 pad.@131,42.375 pad.@131,43.975 pad.@131,45.575 pad.@131,47.175 pad.@131.5,36.775 pad.@131.5,38.375 pad.@131.5,39.975 pad.@131.5,41.575 pad.@131.5,43.175 pad.@131.5,44.775 pad.@131.5,46.375 pad.@132,35.975 pad.@132,37.575 pad.@132,39.175 pad.@132,40.775 pad.@132,42.375 pad.@132,43.975 pad.@132,45.575 pad.@132,47.175 pad.@132.5,36.775 pad.@132.5,38.375 pad.@132.5,39.975 pad.@132.5,41.575 pad.@132.5,43.175 pad.@132.5,44.775 pad.@132.5,46.375 pad.@133,35.975 pad.@133,37.575 pad.@133,39.175 pad.@133,40.775 pad.@133,42.375 pad.@133,43.975 pad.@133,45.575 pad.@133,47.175 pad.@133.5,36.775 pad.@133.5,38.375 pad.@133.5,39.975 pad.@133.5,41.575 pad.@133.5,43.175 pad.@133.5,44.775 pad.@133.5,46.375 pad.@134,35.975 pad.@134,37.575 pad.@134,39.175 pad.@134,40.775 pad.@134,42.375 pad.@134,43.975 pad.@134,45.575 pad.@134,47.175 pad.@134.5,36.775 pad.@134.5,38.375 pad.@134.5,39.975 pad.@134.5,41.575 pad.@134.5,43.175 pad.@134.5,44.775 pad.@134.5,46.375 pad.@135,35.975 pad.@135,37.575 pad.@135,39.175 pad.@135,40.775 pad.@135,42.375 pad.@135,43.975 pad.@135,45.575 pad.@135,47.175 pad.@135.5,36.775 pad.@135.5,38.375 pad.@135.5,39.975 pad.@135.5,41.575 pad.@135.5,43.175 pad.@135.5,44.775 pad.@135.5,46.375 pad.@136,35.975 pad.@136,37.575 pad.@136,39.175 pad.@136,40.775 pad.@136,42.375 pad.@136,43.975 pad.@136,45.575 pad.@136,47.175 pad.@136.5,36.775 pad.@136.5,38.375 pad.@136.5,39.975 pad.@136.5,41.575 pad.@136.5,43.175 pad.@136.5,44.775 pad.@136.5,46.375 pad.@137,35.975 pad.@137,37.575 pad.@137,39.175 pad.@137,40.775 pad.@137,42.375 pad.@137,43.975 pad.@137,45.575 pad.@137,47.175 pad.@137.5,36.775 pad.@137.5,38.375 pad.@137.5,39.975 pad.@137.5,41.575 pad.@137.5,43.175 pad.@137.5,44.775 pad.@137.5,46.375 pad.@138,35.975 pad.@138,37.575 pad.@138,39.175 pad.@138,40.775 pad.@138,42.375 pad.@138,43.975 pad.@138,45.575 pad.@138,47.175 pad.@138.5,36.775 pad.@138.5,38.375 pad.@138.5,39.975 pad.@138.5,41.575 pad.@138.5,43.175 pad.@138.5,44.775 pad.@138.5,46.375 pad.@139,35.975 pad.@139,37.575 pad.@139,39.175 pad.@139,40.775 pad.@139,42.375 pad.@139,43.975 pad.@139,45.575 pad.@139,47.175 pad.@139.5,36.775 pad.@139.5,38.375 pad.@139.5,39.975 pad.@139.5,41.575 pad.@139.5,43.175 pad.@139.5,44.775 pad.@139.5,46.375 pad.@140,35.975 pad.@140,37.575 pad.@140,39.175 pad.@140,40.775 pad.@140,42.375 pad.@140,43.975 pad.@140,45.575 pad.@140,47.175 pad.@140.5,36.775 pad.@140.5,38.375 pad.@140.5,39.975 pad.@140.5,41.575 pad.@140.5,43.175 pad.@140.5,44.775 pad.@140.5,46.375 pad.@141,35.975 pad.@141,37.575 pad.@141,39.175 pad.@141,40.775 pad.@141,42.375 pad.@141,43.975 pad.@141,45.575 pad.@141,47.175 pad.@151,32.5 pad.@151.5,31.5 pad.@152,32.5 pad.@152.5,31.5 pad.@153,32.5 pad.@153.5,31.5 pad.@154,32.5 pad.@154.5,31.5 pad.@155,32.5 pad.@155.5,31.5 pad.@156,32.5 pad.@156.5,31.5 pad.@157,32.5 pad.@157.5,31.5 pad.@158,32.5 Q6.9
SIG232: F1.1 F1.2 TB1.1 | length 12.4
  BOTTOM w0.5: 39.404,118.654 F1.1@40.5,119.75 ; 39.404,120.846 F1.1@40.5,119.75 ; 39.404,123.654 F1.2@40.5,124.75 ; 39.404,125.846 F1.2@40.5,124.75 ; 41.596,118.654 F1.1@40.5,119.75 ; 41.596,120.846 F1.1@40.5,119.75 ; 41.596,123.654 F1.2@40.5,124.75 ; 41.596,125.846 F1.2@40.5,124.75
SIG233: R34.1 R35.2 | length 12.3
  BOTTOM w2: R34.1@64.5,33 R35.2@64.5,45.25
SIG236: R6.2 R7.1 | length 5.1
  BOTTOM w0.8: R7.1@59.35,146.75 R6.2@64.4,146.75
SIG237: C5.1 F1.3 F1.4 L1.4 pad.@73.5,147 R6.1 VAR1.1 | length 29.1
  BOTTOM w0.25: 67.6,145.575 R6.1@67.6,146.75 ; 67.6,147.925 R6.1@67.6,146.75 ; 68.475,146.75 R6.1@67.6,146.75
  BOTTOM w0.4: 70.65,147 C5.1@72,147 ; 72,145.65 C5.1@72,147 ; 72,148.35 C5.1@72,147
  BOTTOM w0.5: 37.26,150.11 VAR1.1@38.25,151.1 ; 37.26,152.09 VAR1.1@38.25,151.1 ; 39.2,150.15 VAR1.1@38.25,151.1 ; 39.24,152.09 VAR1.1@38.25,151.1 ; 39.404,134.154 F1.3@40.5,135.25 ; 39.404,136.346 F1.3@40.5,135.25 ; 39.404,139.154 F1.4@40.5,140.25 ; 39.404,141.346 F1.4@40.5,140.25 ; 41.596,134.154 F1.3@40.5,135.25 ; 41.596,136.346 F1.3@40.5,135.25 ; 41.596,139.154 F1.4@40.5,140.25 ; 41.596,141.346 F1.4@40.5,140.25 ; 73.5,145.7 pad.@73.5,147 ; 73.5,148.3 pad.@73.5,147 ; 74.8,147 pad.@73.5,147
SIG239: C9.2 L1.2 L2.1 | length 5
  BOTTOM w0.4: 55.116,114.116 C9.2@56,115 ; 55.116,115.884 C9.2@56,115 ; 56.884,114.116 C9.2@56,115 ; 56.884,115.884 C9.2@56,115
SIG242: C5.2 L1.1 pad.@50.5,147 R7.2 TB1.2 VAR1.2 | length 16.8
  BOTTOM w0.25: 55.275,146.75 R7.2@56.15,146.75 ; 56.15,145.575 R7.2@56.15,146.75 ; 56.15,147.925 R7.2@56.15,146.75
  BOTTOM w0.4: 52,145.65 C5.2@52,147 ; 52,148.35 C5.2@52,147 ; 53.35,147 C5.2@52,147
  BOTTOM w0.5: 44.76,144.91 VAR1.2@45.75,145.9 ; 44.76,146.89 VAR1.2@45.75,145.9 ; 46.74,144.91 VAR1.2@45.75,145.9 ; 46.74,146.89 VAR1.2@45.75,145.9 ; 49.2,147 pad.@50.5,147 ; 50.5,145.7 pad.@50.5,147 ; 50.5,148.3 pad.@50.5,147
SIG245: R2.2 R3.1 | length 8.1
  BOTTOM w0.3: R2.2@34.75,33.15 34.75,27.4 35.15,27 R3.1@35.15,25.25
SIG246: C8.1 R17.2 R22.1 | length 6.8
  BOTTOM w0.3: R17.2@60.4,22 60.4,22.75 60.65,23 64.35,23 ; C8.1@64.35,22 64.35,23 ; R22.1@64.35,24 64.35,23
SIG247: R3.2 R4.1 | length 2.7
  BOTTOM w0.3: R4.1@38.35,22.5 R3.2@38.35,25.25
SIG248: D11.C D12.C pad.@61,26.675 pad.@66.5,35.3 U1.7 | length 23.9
  TOP w0.3: pad.@61,26.675 65.275,26.675 67.5,28.9 67.5,34.3 pad.@66.5,35.3
  BOTTOM w0.3: pad.@61,26.675 U1.7@62.7,26.675 ; pad.@66.5,35.3 66.5,34.5 66.7,34.3 D12.C@67.55,34.3 68.4,34.3 68.7,34.6 68.7,35.8 69.1,36.2 D11.C@72.05,36.2
SIG250: D7.A R27.1 | length 6.2
  BOTTOM w0.3: R27.1@63.65,30 66.6,30 67.2,29.4 D7.A@67.2,27
SIG255: D17.C R47.2 | length 2.7
  BOTTOM w0.4: R47.2@156.25,49.9 156.975,49.9 157.825,49.05 D17.C@158.55,49.05
SIG256: D4.C R9.2 | length 3.3
  BOTTOM w0.3: D4.C@68.95,31.95 69.55,31.95 71,30.5 R9.2@71,29.9
SIG267: D24.A U6.1 U6.2 | length 137.3
  BOTTOM w0.4: D24.A@74.75,21.55 74.925,21.375 110.25,21.375 112,23.125 112,25.9 115,28.9 120.1,28.9 126.875,22.125 162.625,22.125 166,25.5 166,44.625 161.75,48.875 160.225,48.875 159.75,49.35 159.75,53.125 162.26,55.635 U6.2@163.35,55.635 U6.1@163.35,56.905
SIG270: U6.6 U6.7 | length 1.3
  BOTTOM w0.4: U6.6@156.65,54.365 U6.7@156.65,55.635
SIG278: C10.1 C11.2 pad.@89.365,136.25 pad.@94.1,131.25 R26.2 U2.6 | length 19.2
  TOP w0.8: pad.@89.365,136.25 89.365,134.385 92.5,131.25 pad.@94.1,131.25
  BOTTOM w0.8: C10.1@86,136.15 87.775,136.15 87.875,136.25 pad.@89.365,136.25 U2.6@89.365,138 ; C11.2@91,128 93.725,128 94.1,128.375 R26.2@94.1,129.25 pad.@94.1,131.25
SIG280: D8.C R26.1 | length 3.9
  BOTTOM w0.8: R26.1@95.9,129.25 95.9,131 96.4,131.5 D8.C@97.825,131.5
SIG281: C4.2 R11.2 R14.1 | length 8
  BOTTOM w0.6: C4.2@85,143.9 87.95,143.9 88,143.85 R14.1@90,143.85
  BOTTOM w0.8: C4.2@85,143.9 85,142.875 85.1,142.775 R11.2@85.1,141
SIG283: R10.2 R11.1 | length 2.9
  BOTTOM w0.8: R11.1@81.9,141 81.9,142.775 82,142.875 R10.2@82,143.9
SIG284: D6.A T1.3 U2.8 | length 8.2
  BOTTOM w0.8: U2.8@91.905,138 91.905,140.125 92.25,140.47 92.25,142.325 94.05,142.325 94.375,142 T1.3@95.8,142
SIG285: C18.2 R33.1 | length 2
  BOTTOM w0.8: R33.1@109.75,141.35 C18.2@109.75,143.35
SIG286: D8.A pad.@89,142.4 R23.1 T1.5 | length 19.8
  TOP w0.8: pad.@89,142.4 89,140.875 94.275,135.6 T1.5@95.8,135.6
  BOTTOM w0.8: R23.1@88,142.4 pad.@89,142.4 ; T1.5@95.8,135.6 99.15,135.6 101.175,133.575 D8.A@101.175,131.5
SIG287: C18.1 D14.A T1.9 | length 7.7
  BOTTOM w0.8: T1.9@106.2,145.2 108,145.2 108.05,145.15 C18.1@109.75,145.15 110.65,145.15 112,146.5 D14.A@113.325,146.5
SIG288: R18.1 R21.1 R23.2 U2.5 | length 10.2
  BOTTOM w0.8: R21.1@83.4,136 R18.1@83.4,138 83.4,138.75 84.025,139.375 88,139.375 ; R23.2@88,140.6 88,139.375 ; U2.5@88.095,138 88.095,139.28 88,139.375
SIG290: R8.1 R13.1 U2.4 | length 5.7
  BOTTOM w0.8: R13.1@86.4,128.25 R8.1@86.4,130.5 87.72,130.5 88.095,130.875 U2.4@88.095,132.5
SIG316: R66.2 R67.1 | length 2.1
  BOTTOM w0.8: R66.2@93.5,117.11 R67.1@93.5,119.25
SIG318: R65.2 R66.1 | length 2.1
  BOTTOM w0.8: R65.2@93.5,112.75 R66.1@93.5,114.9
SIG319: R37.2 R38.1 | length 3
  BOTTOM w0.4: R37.2@98.5,65 R38.1@101.5,65
SIG320: R36.2 R37.1 | length 3
  BOTTOM w0.4: R36.2@93.5,65 R37.1@96.5,65
SIG321: R64.2 R65.1 | length 2.2
  BOTTOM w0.8: R64.2@93.5,108.5 R65.1@93.5,110.7
SIG322: R39.2 R40.1 | length 7
  BOTTOM w0.3: R40.1@90,41 R39.2@90,48
SIG323: R63.2 R64.1 | length 2.3
  BOTTOM w0.8: R63.2@93.5,104.25 R64.1@93.5,106.5
SIG327: R67.2 R68.1 | length 2.7
  BOTTOM w0.8: R68.1@93.5,124 93.55,123.95 R67.2@93.55,121.3
SIG328: C24.2 pad.@92.25,50 pad.@92.25,62 R38.2 R39.1 | length 54.4
  TOP w0.4: pad.@92.25,50 pad.@92.25,62
  BOTTOM w0.3: R39.1@90,50 pad.@92.25,50
  BOTTOM w0.4: C24.2@101,72.25 86.75,72.25 85.5,71 85.5,64.125 87.625,62 pad.@92.25,62 100.5,62 R38.2@101.5,63
SIG332: R54.2 R55.1 | length 2.3
  BOTTOM w0.5: R55.1@160.6,65 R54.2@162.9,65
SIG333: R53.2 R54.1 | length 4
  BOTTOM w0.5: R54.1@165.1,65 R53.2@165.1,69
SIG334: R52.2 R53.1 | length 2.3
  BOTTOM w0.5: R52.2@160.6,69 R53.1@162.9,69
SIG335: R55.2 R56.1 | length 4
  BOTTOM w0.5: R56.1@158.4,61 R55.2@158.4,65
SIG341: Q2.C Q5.C R50.2 R51.2 | length 15.8
  BOTTOM w0.4: R51.2@82.85,122 82.85,121.2 80.5,118.85 Q5.C@80.5,113.25 Q2.C@84.5,113.25 R50.2@84.5,111.15
SIG345: R42.2 U3.8 | length 15.4
  BOTTOM w0.4: U3.8@104.25,25.845 104.25,23.5 104.75,23 109.8,23 110.5,23.7 110.5,26.75 112,28.25 R42.2@112,29.4
SIG348: C29.1 D19.C R51.1 | length 8.8
  BOTTOM w0.4: R51.1@84.65,122 86.125,122 87.075,121.05 D19.C@88.3,121.05 89.2,121.05 90.6,119.65 C29.1@90.6,117.75
SIG351: R20.1 U3.4 | length 2.6
  BOTTOM w0.4: R20.1@96.15,29.75 97.155,29.75 97.25,29.655 U3.4@98.75,29.655
SIG353: Q2.B R30.1 | length 7.2
  BOTTOM w0.4: Q2.B@83.55,115.75 83.55,115 84.05,114.5 85.875,114.5 86.375,114 86.375,112.25 86.875,111.75 R30.1@87.6,111.75
SIG354: C7.1 U3.2 | length 4.9
  BOTTOM w0.3: U3.2@98.75,27.115 100.1,27.115 100.65,26.565 C7.1@100.65,23.75
SIG356: C16.1 R29.1 U3.5 | length 5.7
  BOTTOM w0.3: C16.1@102.65,34 R29.1@102.65,31.75 102.65,30.105 103.1,29.655 U3.5@104.25,29.655
SIG357: Q3.B R31.1 | length 4.9
  BOTTOM w0.3: R31.1@77.5,26.35 77.5,22.55 77.75,22.3 Q3.B@78.5,22.3
SIG358: C14.1 R29.2 | length 2.6
  BOTTOM w0.3: C14.1@98.6,32.5 99.4,32.5 100.15,31.75 R29.2@100.85,31.75
SIG359: C6.1 D5.C R15.1 R19.2 U3.3 | length 19.6
  BOTTOM w0.3: R19.2@97,34.35 97,31.5 97.5,31 99.875,31 100.125,30.75 100.125,28.51 100,28.385 U3.3@98.75,28.385
  BOTTOM w0.4: D5.C@91.45,26.45 92.7,26.45 93,26.75 96.15,26.75 ; R15.1@96.15,25.75 96.15,26.75 ; U3.3@98.75,28.385 97.635,28.385 97,27.75 C6.1@96.15,27.75 96.15,26.75
SIG381: D21.A Q8.G R78.2 R82.1 | length 14
  BOTTOM w0.4: R78.2@109,95.4 110.375,95.4 110.45,95.325 111.75,95.325 112.875,95.325 112.95,95.25 R82.1@114.35,95.25 114.35,94.61 Q8.G@119.96,89
SIG383: D20.A pad.@100,97.125 Q7.G R77.2 R81.1 | length 13.6
  TOP w0.4: Q7.G@99.96,89 99.96,91.5 100,91.54 pad.@100,97.125
  BOTTOM w0.4: R77.2@97,98.4 98.5,98.4 98.575,98.325 100,98.325 pad.@100,97.125 R81.1@100,95.9
SIG387: D20.C R74.1 R77.1 | length 5.6
  BOTTOM w0.4: R74.1@97,104.15 R77.1@97,101.6 98.5,101.6 98.575,101.675 D20.C@100,101.675
SIG392: D21.C R76.1 R78.1 | length 4.8
  BOTTOM w0.4: R76.1@109,100.65 R78.1@109,98.6 110.375,98.6 110.45,98.675 D21.C@111.75,98.675
SIG395: C46.2 R73.2 R85.1 R86.1 | length 9.3
  BOTTOM w0.4: C46.2@116.65,112.5 117.375,112.5 118.4,113.525 R86.1@118.4,114.75 118.4,115.4 119.4,116.4 R73.2@119.4,118.25 R85.1@119.4,120.25
SIG396: C44.2 C51.1 C52.1 pad.@114.75,116.125 pad.@118,109.5 R117.2 | length 15.7
  TOP w0.4: pad.@114.75,116.125 115.25,115.625 115.25,112.25 pad.@118,109.5
  BOTTOM w0.4: R117.2@112,118.35 112.9,118.35 113,118.25 C51.1@113.85,118.25 ; C52.1@113.85,120.25 C51.1@113.85,118.25 ; pad.@114.75,116.125 113.85,117.025 C51.1@113.85,118.25 ; C44.2@116.65,109.5 pad.@118,109.5
SIG401: C28.1 R59.1 R71.2 R72.2 U5.8 | length 10
  BOTTOM w0.4: U5.8@108.695,121 108.695,122.1 108.945,122.35 110,122.35 ; C28.1@110,123.85 110,122.35 ; R71.2@116,122.35 R72.2@114,122.35 R59.1@112,122.35 110,122.35
SIG404: C30.1 R70.2 | length 2
  BOTTOM w0.4: R70.2@114.75,110.65 C30.1@114.75,112.6
SIG406: R117.1 U5.7 | length 6.2
  BOTTOM w0.4: U5.7@107.425,121 107.425,119.75 107.675,119.5 109.5,119.5 110.15,120.15 R117.1@112,120.15
SIG407: C38.2 D22.C pad.@100,105.75 pad.@102.345,114 U5.14 | length 18.2
  TOP w0.4: pad.@100,105.75 100,111.655 pad.@102.345,114
  BOTTOM w0.4: C38.2@97.75,116.9 102,116.9 102.345,116.555 U5.14@102.345,115.5 pad.@102.345,114 ; D22.C@100,104.075 pad.@100,105.75
SIG409: R97.2 ZD2.A | length 2.2
  BOTTOM w0.4: ZD2.A@114.175,106.5 R97.2@116.35,106.5
SIG415: C50.2 R88.2 | length 2.5
  BOTTOM w0.4: R88.2@176.5,130.4 176.5,129.15 176.65,129 C50.2@176.65,128
SIG416: C55.1 U9.3 | length 2.4
  BOTTOM w0.4: U9.3@197.95,140.6 197.95,141.75 198.05,141.85 C55.1@198.05,143
SIG417: C49.1 R89.1 | length 4.7
  BOTTOM w0.4: R89.1@176.75,121.85 178.6,121.85 179.1,121.35 C49.1@179.1,119.25
SIG418: C53.1 U8.3 | length 2.4
  BOTTOM w0.4: U8.3@197.95,124.1 197.95,125.25 198.05,125.35 C53.1@198.05,126.5
SIG420: C54.1 R98.2 U8.4 | length 8
  BOTTOM w0.4: U8.4@197.95,121.4 199,121.4 199.7,122.1 C54.1@200.5,122.1 201.5,122.1 202,121.6 R98.2@202,118.15
SIG422: Q13.4 R94.1 | length 2.6
  BOTTOM w0.4: R94.1@193.5,113.9 Q13.4@196.095,113.9
SIG423: Q11.4 R95.1 | length 2.6
  BOTTOM w0.4: R95.1@180.5,113.9 Q11.4@183.095,113.9
SIG425: pad.@178.5,133.6 pad.@191.5,133.6 pad.@191.5,138.35 R92.2 R93.2 R96.2 U9.1 | length 27.4
  TOP w0.4: pad.@178.5,133.6 pad.@191.5,133.6 pad.@191.5,138.35
  BOTTOM w0.4: pad.@178.5,133.6 R93.2@180.25,133.6 ; pad.@191.5,133.6 R92.2@193.5,133.6 ; pad.@191.5,138.35 R96.2@193.5,138.35 194.5,138.35 196.05,139.9 U9.1@196.05,140.6
SIG426: Q12.4 R92.1 | length 2.6
  BOTTOM w0.4: R92.1@193.5,130.4 Q12.4@196.095,130.4
SIG430: Q10.4 R93.1 | length 2.8
  BOTTOM w0.4: R93.1@180.25,130.4 Q10.4@183.095,130.4
SIG431: pad.@178.625,117.1 pad.@191.5,117.1 pad.@191.5,122.35 R91.2 R94.2 R95.2 U8.1 | length 27.8
  TOP w0.4: pad.@178.625,117.1 pad.@191.5,117.1 pad.@191.5,122.35
  BOTTOM w0.4: pad.@178.625,117.1 R95.2@180.5,117.1 ; pad.@191.5,117.1 R94.2@193.5,117.1 ; pad.@191.5,122.35 R91.2@193.5,122.35 195.15,122.35 196.05,123.25 U8.1@196.05,124.1
SIG435: C58.1 R99.1 U9.4 | length 6.8
  BOTTOM w0.4: U9.4@197.95,137.9 199.025,137.9 199.475,138.35 C58.1@200.5,138.35 201.275,138.35 202,137.625 R99.1@202,135.4
SIG438: R109.2 R110.1 | length 2.7
  BOTTOM w0.4: R109.2@177,55.4 178.5,55.4 178.6,55.5 R110.1@179.65,55.5
SIG439: R110.2 R111.1 | length 3
  BOTTOM w0.4: R110.2@182.85,55.5 182.85,54 182.9,53.95 R111.1@182.9,52.5
SIG440: Q16.4 R116.1 | length 2.3
  BOTTOM w0.4: R116.1@188,33.15 188.095,33.245 Q16.4@188.095,35.4
SIG441: C65.1 C78.2 C80.1 C81.1 Q14.5 Q15.5 Q16.5 TB2.3 TB2.4 U11.1 U11.6 | length 33.6
  BOTTOM w0.3: 188.25,44.25 C80.1@189.1,44.25 ; C78.2@188.75,47 188.75,49.4 C81.1@189.1,49.75 ; 189.1,43.4 C80.1@189.1,44.25 ; 189.1,45.1 C80.1@189.1,44.25 ; 189.95,44.25 C80.1@189.1,44.25
  BOTTOM w0.4: C65.1@176.5,35.4 177.775,35.4 177.83,35.345 U11.1@179,35.345 180.97,35.345 182.25,36.625 182.25,37.885 ; 183.15,37.885 U11.6@184.5,37.885
  BOTTOM w1: 201.374,46.374 TB2.4@203,48 ; 201.374,49.626 TB2.4@203,48 ; 201.374,57.374 TB2.3@203,59 ; 201.374,60.626 TB2.3@203,59 ; 204.626,46.374 TB2.4@203,48 ; 204.626,49.626 TB2.4@203,48 ; 204.626,57.374 TB2.3@203,59 ; 204.626,60.626 TB2.3@203,59
SIG442: C73.2 U11.8 | length 2.8
  BOTTOM w0.3: C73.2@184.4,32.6 184.4,33.2 184.5,33.3 U11.8@184.5,35.345
SIG444: Q15.4 R115.1 | length 2.3
  BOTTOM w0.4: R115.1@194.5,33.15 194.595,33.245 Q15.4@194.595,35.4
SIG445: Q14.4 R113.1 | length 2.3
  BOTTOM w0.4: R113.1@201,33.15 201.095,33.245 Q14.4@201.095,35.4
SIG446: R104.1 U11.2 | length 2.8
  BOTTOM w0.4: R104.1@176.5,37.35 177.275,37.35 178.01,36.615 U11.2@179,36.615
SIG447: R111.2 R112.1 | length 3
  BOTTOM w0.4: R111.2@186.1,52.5 186.1,53.95 186.15,54 R112.1@186.15,55.5
SIG452: R100.2 R101.1 ZD3.C | length 14
  BOTTOM w0.3: R101.1@163.5,76.6 166.775,76.6 168.025,75.35 168.75,75.35 ; ZD3.C@169,73.575 169,75.1 ; 168.75,75.35 169.25,75.35 ; 168.75,75.35 R100.2@171.75,75.35 169.25,75.35 ; 168.75,75.35 169,75.1 ; 169,75.1 169.25,75.35
SIG454: C64.1 R105.1 | length 3.1
  BOTTOM w0.3: R105.1@160.5,78.85 161.15,78.85 161.5,79.2 161.5,79.9 161.85,80.25 C64.1@162.6,80.25
SIG455: C68.1 R106.2 R107.1 | length 7.8
  BOTTOM w0.3: C68.1@162.75,82.35 R107.1@165,82.35 166.15,82.35 167.625,80.875 167.625,79.675 168.05,79.25 R106.2@168.6,79.25
SIG458: C70.2 D25.A D26.C R114.1 | length 13.5
  BOTTOM w0.3: D26.C@167.55,84.2 167.55,85.175 167.875,85.5 168.95,85.5 ; C70.2@168.4,91.75 168.4,88.975 168.95,88.425 D25.A@168.95,87.75 168.95,85.5 ; R114.1@171.75,83.65 171.75,85.25 171.5,85.5 168.95,85.5
SIG460: C64.2 pad.@165.4,81.125 pad.@165.4,87.75 R103.2 U10.1 | length 11.6
  TOP w0.3: pad.@165.4,81.125 pad.@165.4,87.75
  BOTTOM w0.3: C64.2@164.4,80.25 165.25,80.25 165.4,80.4 ; U10.1@164.45,86.35 165,86.35 165.4,86.75 pad.@165.4,87.75 ; pad.@165.4,81.125 165.4,80.4 ; R103.2@166.5,80.4 165.4,80.4
SIG461: R24.2 R25.1 U1.5 | length 11.3
  BOTTOM w0.3: U1.5@62.7,27.975 63.3,27.975 64.125,28.8 65.75,28.8 66,28.55 66,26.625 66.625,26 R24.2@69.35,26 R25.1@69.35,24
SIG462: R16.2 R17.1 U1.1 | length 4.1
  BOTTOM w0.3: R17.1@58.6,22 R16.2@58.6,24 58.6,25 58.8,25.2 U1.1@58.8,26.025
SIG464: C34.1 R79.2 R80.1 U5.9 | length 7.2
  BOTTOM w0.4: U5.9@108.695,115.5 108.695,114.43 109.025,114.1 C34.1@110.75,114.1 ; R79.2@110.75,112.15 C34.1@110.75,114.1 ; R80.1@112.75,114.1 C34.1@110.75,114.1
SIG466: C27.1 pad.@110.25,118.625 pad.@116.75,119.25 R73.1 U5.6 | length 18.6
  TOP w0.4: pad.@110.25,118.625 116.125,118.625 pad.@116.75,119.25
  BOTTOM w0.4: C27.1@108,123.85 108,123 107.75,122.75 106.405,122.75 106.155,122.5 U5.6@106.155,121 106.155,119.72 107.25,118.625 pad.@110.25,118.625 ; pad.@116.75,119.25 117.25,119.25 117.6,118.9 R73.1@117.6,118.25
SIG469: R60.2 R61.1 R62.1 | length 4
  BOTTOM w0.3: R62.1@38.6,31.5 R60.2@38.6,33.5 R61.1@38.6,35.5
SIG470: R48.2 U4.2 | length 9.8
  BOTTOM w0.3: U4.2@43.05,30.175 44.45,30.175 44.75,29.875 44.75,27.15 43.85,26.25 R48.2@43.85,26 43.85,24.75 44.75,23.85 44.75,22.625
SIG471: R62.2 R69.1 U4.3 | length 4.8
  BOTTOM w0.3: R69.1@40.4,29.5 40.4,30.5 ; R62.2@40.4,31.5 40.4,30.5 ; U4.3@43.05,30.825 42.075,30.825 41.75,30.5 40.4,30.5
SIG489: D7.C R22.2 U1.6 | length 6.2
  BOTTOM w0.3: U1.6@62.7,27.325 63.5,27.325 63.75,27.075 63.75,26.3 64,26.05 D7.C@64.8,26.05 65.65,26.05 66.15,25.55 R22.2@66.15,24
